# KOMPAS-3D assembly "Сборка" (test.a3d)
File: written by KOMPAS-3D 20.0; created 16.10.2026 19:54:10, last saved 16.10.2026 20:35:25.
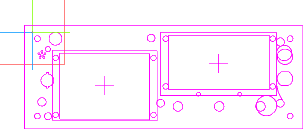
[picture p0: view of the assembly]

Document properties: Полное имя файла: D:\myProjects\Progect_esp32\box_compas\корпус\test.a3d

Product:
- Part/product: Сборка
    Масса: 0.0227288
  - Component [detail]: Деталь  | Материал: Фанера, береза,ФСФ ВВ/С ГОСТ 3916.1-2018 (density 760 kg/m3); Масса: 0.0227288; source file: back_panel_v2.m3d

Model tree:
1. Эскиз:1  (with: Элемент выдавливания:1, Элемент выдавливания:6, Элемент выдавливания:19, Элемент выдавливания:23, Элемент выдавливания:36, Элемент вращения:3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)
2. Эскиз:2

Referenced files in D:\myProjects\Progect_esp32\box_compas\корпус\: back_panel_v2.m3d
